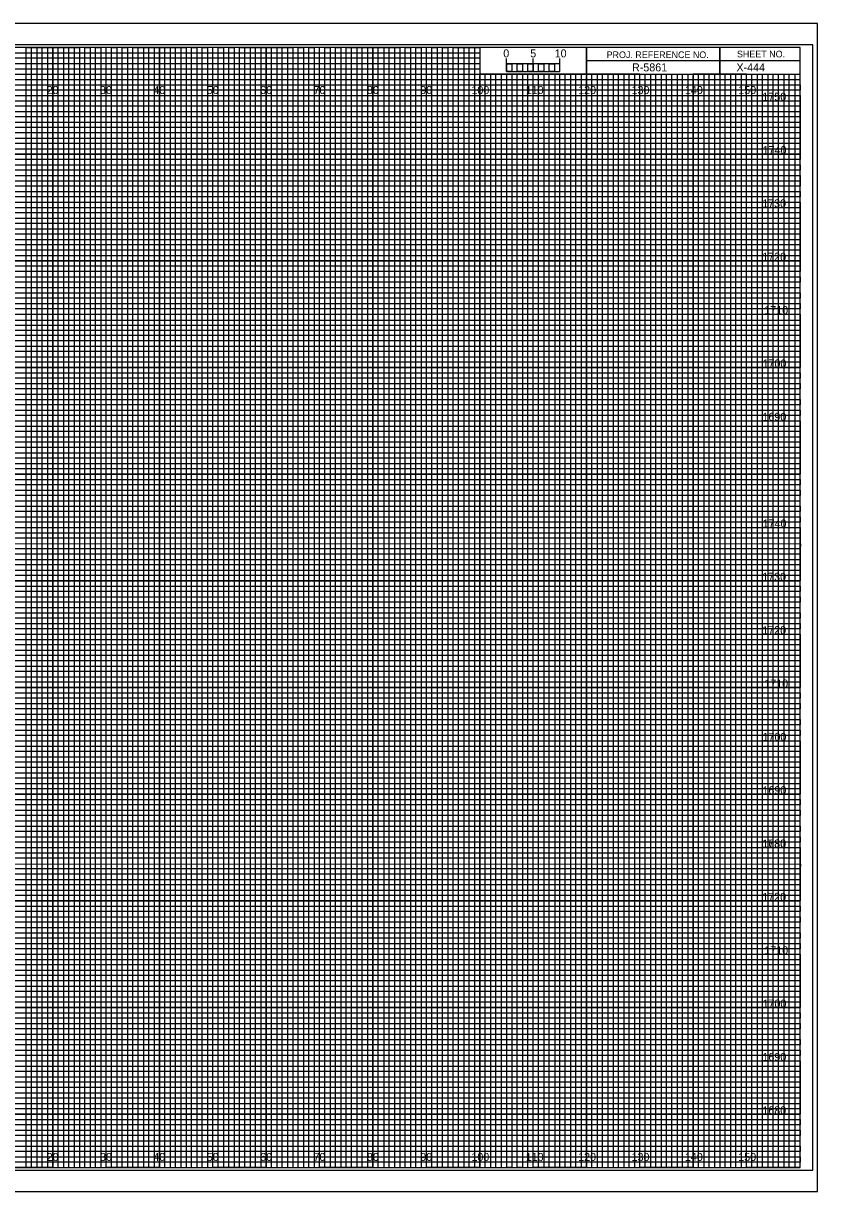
# Model space of a CAD drawing. Extents: x -13 to 323, y -5 to 1314.
# Drawn here: x 174.5 to 323.3, y 655.5 to 874.5 of the extents above; entities that cross this region are included whole.
import ezdxf

# ---------------------------------------------------------------- set-up
doc = ezdxf.new("R2010")
doc.units = 0
for name, color, linetype in [('Prop XS Bar Scale Labels', 7, 'Continuous'), ('Prop XS Project Number', 7, 'Continuous'), ('Prop XS Sheet Number', 7, 'Continuous'), ('Raster_Level_0', 7, 'Continuous'), ('Scratch_Level_3', 7, 'Continuous'), ('Sheet Cross Section CELL', 7, 'Continuous'), ('Sheet Cross Section Grid Major CELL', 7, 'Continuous'), ('Sheet Cross Section Grid Middle CELL', 7, 'Continuous'), ('Sheet Cross Section Grid Minor 1 CELL', 7, 'Continuous'), ('Sheet Cross Section Grid Minor 2 CELL', 7, 'Continuous'), ('Sheet Cross Section Scale CELL', 7, 'Continuous'), ('Sheet Cutting Line CELL', 7, 'Continuous'), ('Sheet DOT Grid CELL', 7, 'Continuous'), ('Sheet Plot Border Inside CELL', 7, 'Continuous'), ('Sheet Plot Border Outside CELL', 7, 'Continuous')]:
    doc.layers.add(name, color=color, linetype=linetype)

msp = doc.modelspace()

# ---------------------------------------------------------------- linework, layer by layer
at = {"layer": 'Sheet Cross Section CELL'}
for p, q in [((305, 870), (305, 865)), ((305, 865), (305, 870)), ((280, 867.5), (280, 865)), ((320, 867.49), (280, 867.49)), ((280, 865), (320, 865))]:
    msp.add_line(p, q, dxfattribs=at)
for points in [[(320, 870), (0, 870), (0, 660), (320, 660)], [(280, 870), (260, 870), (260, 865.03), (280, 865.03)], [(320, 870), (280, 870), (280, 865), (320, 865)]]:
    msp.add_lwpolyline(points, close=True, dxfattribs=at)
at = {"layer": 'Sheet Cross Section Grid Major CELL'}
for p, q in [((190, 870), (180, 870)), ((180, 870), (180, 660)), ((190, 660), (190, 870)), ((210, 870), (200, 870)), ((200, 870), (200, 660)), ((210, 660), (210, 870)), ((230, 870), (220, 870)), ((220, 870), (220, 660)), ((230, 660), (230, 870)), ((250, 870), (240, 870)), ((240, 870), (240, 660)), ((250, 660), (250, 870)), ((260, 870), (260, 660)), ((270, 660), (270, 865)), ((290, 865), (280, 865)), ((280, 865), (280, 660)), ((290, 660), (290, 865)), ((310, 865), (300, 865)), ((300, 865), (300, 660)), ((310, 660), (310, 865)), ((180, 660), (170, 660)), ((200, 660), (190, 660)), ((220, 660), (210, 660)), ((240, 660), (230, 660)), ((260, 660), (250, 660)), ((280, 660), (270, 660)), ((300, 660), (290, 660)), ((320, 660), (310, 660)), ((320, 660), (320, 660))]:
    msp.add_line(p, q, dxfattribs=at)
for points in [[(0, 860), (320, 860), (320, 850), (0, 850)], [(0, 840), (320, 840), (320, 830), (0, 830)], [(0, 820), (320, 820), (320, 810), (0, 810)], [(0, 800), (320, 800), (320, 790), (0, 790)], [(0, 780), (320, 780), (320, 770), (0, 770)], [(0, 760), (320, 760), (320, 750), (0, 750)], [(0, 740), (320, 740), (320, 730), (0, 730)], [(0, 720), (320, 720), (320, 710), (0, 710)], [(0, 700), (320, 700), (320, 690), (0, 690)], [(0, 680), (320, 680), (320, 670), (0, 670)]]:
    msp.add_lwpolyline(points, dxfattribs=at)
at = {"layer": 'Sheet Cross Section Grid Middle CELL'}
for points in [[(165, 660), (175, 660), (175, 870), (185, 870), (185, 660), (195, 660), (195, 870), (205, 870), (205, 660), (215, 660), (215, 870), (225, 870), (225, 660), (235, 660), (235, 870), (245, 870), (245, 660), (255, 660), (255, 870), (259.93, 870), (260, 870), (260, 865), (264.99, 865), (264.99, 660), (275, 660), (275, 865), (285, 865), (285, 660), (295, 660), (295, 865), (305, 865), (305, 660), (315, 660), (315, 865)], [(0, 865), (275, 865)], [(0, 845), (320, 845), (320, 855), (0, 855)], [(0, 825), (320, 825), (320, 835), (0, 835)], [(0, 805), (320, 805), (320, 815), (0, 815)], [(0, 785), (320, 785), (320, 795), (0, 795)], [(0, 765), (320, 765), (320, 775), (0, 775)], [(0, 745), (320, 745), (320, 755), (0, 755)], [(0, 725), (320, 725), (320, 735), (0, 735)], [(0, 705), (320, 705), (320, 715), (0, 715)], [(0, 685), (320, 685), (320, 695), (0, 695)], [(0, 665), (320, 665), (320, 675), (0, 675)]]:
    msp.add_lwpolyline(points, dxfattribs=at)
at = {"layer": 'Sheet Cross Section Grid Minor 1 CELL'}
for p, q in [((0, 869), (260, 869)), ((260, 867.98), (0, 867.98)), ((260, 869), (260, 867.98)), ((0, 867), (260, 867)), ((260, 865.89), (0, 865.89)), ((260, 867), (260, 865.89)), ((0, 864), (320, 864))]:
    msp.add_line(p, q, dxfattribs=at)
for points in [[(0, 863), (270, 863), (320, 863), (320, 862), (0, 862)], [(0, 861), (320, 861), (320, 859), (0, 859)], [(0, 858), (320, 858), (320, 857), (0, 856.98)], [(0, 856), (320, 856), (320, 854), (0, 854)], [(0, 853), (320, 853), (320, 852), (0, 852)], [(0, 851), (320, 851), (320, 849), (0, 849)], [(0, 848), (320, 848), (320, 847), (0, 847)], [(0, 846), (320, 846), (320, 844), (0, 844)], [(0, 843), (320, 843), (320, 842), (0, 842)], [(0, 841), (320, 841), (320, 839), (0, 839)], [(0, 838), (320, 838), (320, 837), (0, 837)], [(0, 836), (320, 836), (320, 833.95), (320, 833), (320, 832), (0, 832)], [(0, 834), (320, 834), (320, 833), (0, 833)], [(0, 831), (320, 831), (320, 829), (0, 829.03)], [(0, 829.03), (320, 829), (320, 828), (0, 828)], [(0, 827), (320, 827), (320, 826), (0, 826)], [(0, 824), (320, 824), (320, 823), (0, 823)], [(0, 822), (320, 822), (320, 821), (0, 821)], [(-0.07, 818.89), (320, 818.89), (320, 817.88), (-0.07, 817.88)], [(0, 817), (320, 817), (320, 816), (0, 816)], [(0, 814), (320, 814), (320, 813), (0, 813)], [(0, 812), (320, 812), (320, 811), (0, 811)], [(0, 809), (320, 809), (320, 808), (0, 808)], [(0, 807), (320, 807), (320, 806), (0, 806)], [(0, 804), (320, 804), (320, 803), (0, 803)], [(0, 802), (320, 802), (320, 801), (0, 801)], [(0, 799), (320, 799), (319.99, 797.98), (0, 798)], [(0, 797), (320, 797), (320, 796), (0, 796)], [(0, 794), (320, 794), (320, 793), (0, 793)], [(0, 792), (320, 792), (320, 791), (0, 791)], [(0, 789), (320, 789), (320, 788), (0, 788)], [(0, 787), (320, 787), (320, 786), (0, 786)], [(0, 784), (320, 784), (320, 783), (0, 783)], [(0, 782), (320, 782), (320, 781), (0, 781)], [(0, 779), (320, 779), (320, 778), (0, 778)], [(0, 776.99), (320.07, 776.91), (320, 776), (0, 776)], [(0, 774), (320, 774), (320, 773), (0, 773)], [(0, 772), (320, 772), (320, 771), (0, 771)], [(0, 769), (320, 769), (320, 768), (0, 768)], [(0, 767), (320, 767), (320, 766), (0, 766)], [(0, 764), (320, 764), (320, 763), (0, 763)], [(0, 762), (320, 762), (320, 761), (0, 761)], [(0, 759), (320, 759), (320, 758), (0, 758)], [(0, 757), (320, 757), (320, 756), (0, 756)], [(0, 754), (320, 754), (320, 753), (0, 753)], [(0, 752), (320, 752), (320, 751), (0, 751)], [(0, 749), (320, 749), (320, 748), (0, 748)], [(0, 747), (320, 747), (320, 746), (0, 746)], [(0, 744), (320, 744), (320, 743), (0, 743)], [(0, 742), (320, 742), (320, 741), (0, 741)], [(0, 739), (320, 739), (319.99, 737.98), (0, 738)], [(0, 737), (320, 737), (320, 736), (0, 736)], [(0, 734), (320, 734), (320, 733), (0, 733)], [(0, 732), (320, 732), (320, 731), (0, 731)], [(0, 729), (320, 729), (320, 728), (0, 728)], [(0, 727), (320, 727), (320, 726), (0, 726)], [(0, 724), (320, 724), (320, 723), (0, 723)], [(0, 722), (320, 722), (320, 721), (0, 721)], [(0, 719), (320, 719), (320, 718), (0, 718)], [(0, 716.99), (320.07, 716.91), (320, 716), (0, 716)], [(0, 714), (320, 714), (320, 713), (0, 713)], [(0, 712), (320, 712), (320, 711), (0, 711)], [(0, 709), (320, 709), (320, 708), (0, 708)], [(0, 707), (320, 707), (320, 706), (0, 706)], [(0, 704), (320, 704), (320, 703), (0, 703)], [(0, 702), (320, 702), (320, 701), (0, 701)], [(0, 699), (320, 699), (320, 698), (0, 698)], [(0, 697), (320, 697), (320, 696), (0, 696)], [(0, 694), (320, 694), (320, 693), (0, 693)], [(0, 692), (320, 692), (320, 691), (0, 691)], [(0, 689), (320, 689), (320, 688), (0, 688)], [(0, 687), (320, 687), (320, 686), (0, 686)], [(0, 684), (320, 684), (320, 683), (0, 683)], [(0, 682), (320, 682), (320, 681), (0, 681)], [(0, 679), (320, 679), (320, 678), (0, 678)], [(0, 677), (320, 677), (320, 676), (0, 676)], [(0, 674), (320, 674), (320, 673), (0, 673)], [(0, 672), (320, 672), (320, 671), (0, 671)], [(0, 669), (320, 669), (320, 668), (0, 668)], [(0, 667), (320, 667), (320, 666), (0, 666)], [(0, 664), (320, 664), (320, 663), (0, 663)], [(0, 662), (320, 662), (320, 661), (0, 661)]]:
    msp.add_lwpolyline(points, dxfattribs=at)
at = {"layer": 'Sheet Cross Section Grid Minor 2 CELL'}
for p, q in [((267, 865), (266.01, 865)), ((266.01, 865), (266.01, 660)), ((267, 660), (267, 865)), ((269, 865), (268, 865)), ((268, 865), (268, 660)), ((269, 660), (269, 865)), ((266.01, 660), (265, 660)), ((268, 660), (267, 660))]:
    msp.add_line(p, q, dxfattribs=at)
for points in [[(175, 660), (176, 660), (176, 870), (177, 870), (177, 660)], [(177, 660), (178, 660), (178, 870), (179, 870), (179, 660)], [(180, 660), (181, 660), (181, 870), (182, 870), (182, 660)], [(182, 660), (183, 660), (183, 870), (184, 870), (184, 660)], [(185, 660), (186, 660), (186, 870), (187, 870), (187, 660)], [(187, 660), (188, 660), (188, 870), (189, 870), (189, 660)], [(190, 660), (191, 660), (191, 870), (192, 870), (192, 660)], [(192, 660), (193, 660), (193, 870), (194, 870), (194, 660)], [(195, 660), (196, 660), (196, 870), (197, 870), (197, 660)], [(197, 660), (198, 660), (198, 870), (199, 870), (199, 660)], [(200, 660), (201, 660), (201, 870), (202, 870), (202, 660)], [(202, 660), (203, 660), (203, 870), (204, 870), (204, 660)], [(205, 660), (206, 660), (206, 870), (207, 870), (207, 660)], [(207, 660), (208, 660), (208, 870), (209, 870), (209, 660)], [(210, 660), (211, 660), (211, 870), (212, 870), (212, 660)], [(212, 660), (213, 660), (213, 870), (214, 870), (214, 660)], [(215, 660), (216, 660), (216, 870), (217, 870), (217, 660)], [(217, 660), (218, 660), (218, 870), (219, 870), (219, 660)], [(220, 660), (221, 660), (221, 870), (222, 870), (222, 660)], [(222, 660), (223, 660), (223, 870), (224, 870), (224, 660)], [(225, 660), (226, 660), (226, 870), (227, 870), (227, 660)], [(227, 660), (228, 660), (228, 870), (229, 870), (229, 660)], [(230, 660), (231, 660), (231, 870), (232, 870), (232, 660)], [(232, 660), (233, 660), (233, 870), (234, 870), (234, 660)], [(235, 660), (236, 660), (236, 870), (237, 870), (237, 660)], [(237, 660), (238, 660), (238, 870), (239, 870), (239, 660)], [(240, 660), (241, 660), (241, 870), (242, 870), (242, 660)], [(242, 660), (243, 660), (243, 870), (244, 870), (244, 660)], [(245, 660), (246, 660), (246, 870), (247, 870), (247, 660)], [(247, 660), (248, 660), (248, 870), (249, 870), (249, 660)], [(250, 660), (251, 660), (251, 870), (252, 870), (252, 660)], [(252, 660), (253, 660), (253, 870), (254, 870), (254, 660)], [(255, 660), (256, 660), (256, 870), (257, 870), (257, 660)], [(257, 660), (258, 660), (258, 870), (259, 870), (259, 660)], [(260, 660), (261, 660), (261, 865), (262.02, 865), (262.02, 660)], [(262, 660), (263, 660), (263, 865), (263.99, 865), (263.99, 660)], [(270, 660), (270.98, 660), (270.98, 865), (272, 865), (272, 660)], [(272, 660), (273, 660), (273, 865), (274.05, 865), (274.05, 660)], [(275, 660), (276, 660), (276, 865), (277, 865), (277, 660)], [(277, 660), (278, 660), (278, 865), (279, 865), (279, 660)], [(280, 660), (281, 660), (281, 865), (282, 865), (282, 660)], [(282, 660), (283, 660), (283, 865), (284, 865), (284, 660)], [(285, 660), (286, 660), (286, 865), (287, 865), (287, 660)], [(287, 660), (288, 660), (288, 865), (289, 865), (289, 660)], [(290, 660), (291, 660), (291, 865), (292, 865), (292, 660)], [(292, 660), (293, 660), (293, 865), (294, 865), (294, 660)], [(295, 660), (296, 660), (296, 865), (297, 865), (297, 660)], [(297, 660), (298, 660), (298, 865), (299, 865), (299, 660)], [(300, 660), (301, 660), (301, 865), (302, 865), (302, 660)], [(302, 660), (303, 660), (303, 865), (304, 865), (304, 660)], [(305, 660), (306, 660), (306, 865), (307, 865), (307, 660)], [(307, 660), (308, 660), (308, 865), (309, 865), (309, 660)], [(310, 660), (311, 660), (311, 865), (312, 865), (312, 660)], [(312, 660), (313, 660), (313, 865), (314, 865), (314, 660)], [(315, 660), (316, 660), (316, 865), (317, 865), (317, 660)], [(317, 660), (318, 660), (318, 865), (319, 865), (319, 660)]]:
    msp.add_lwpolyline(points, dxfattribs=at)
at = {"layer": 'Sheet Cross Section Scale CELL'}
for p, q in [((265, 865.49), (265, 867.9)), ((265, 866.9), (265, 867.9)), ((270, 865.49), (270, 867.9)), ((275, 865.49), (275, 867.9)), ((275, 866.9), (275, 867.9))]:
    msp.add_line(p, q, dxfattribs=at)
for points in [[(275, 866.9), (265, 866.9), (265, 865.49), (275, 865.49)], [(265, 866.9), (266, 866.9), (266, 865.49), (265, 865.49)], [(267, 866.9), (268, 866.9), (268, 865.49), (267, 865.49)], [(269, 866.9), (270, 866.9), (270, 865.49), (269, 865.49)], [(271, 866.9), (272, 866.9), (272, 865.49), (271, 865.49)], [(273, 866.9), (274, 866.9), (274, 865.49), (273, 865.49)]]:
    msp.add_lwpolyline(points, close=True, dxfattribs=at)
at = {"layer": 'Sheet Cutting Line CELL'}
for p, q in [((323.3, 874.5), (-13.4, 874.5)), ((-13.4, 655.5), (323.3, 655.5))]:
    msp.add_line(p, q, dxfattribs=at)
at = {"layer": 'Sheet DOT Grid CELL'}
for p, q in [((180, 660), (180, 870)), ((190, 660), (190, 870)), ((200, 660), (200, 870)), ((210, 660), (210, 870)), ((220, 660), (220, 870)), ((230, 660), (230, 870)), ((240, 660), (240, 870)), ((250, 660), (250, 870)), ((260, 660), (260, 864.69)), ((270, 660), (270, 864.69)), ((280, 660), (280, 864.69)), ((290, 660), (290, 864.69)), ((300, 660), (300, 864.69)), ((310, 660), (310, 864.69)), ((0, 860), (320, 860)), ((0, 850), (320, 850)), ((0, 840), (320, 840)), ((0, 830), (320, 830)), ((0, 820), (320, 820)), ((0, 810), (320, 810)), ((0, 800), (320, 800)), ((0, 790), (320, 790)), ((0, 780), (320, 780)), ((0, 770), (320, 770)), ((0, 760), (320, 760)), ((0, 750), (320, 750)), ((0, 740), (320, 740)), ((0, 730), (320, 730)), ((0, 720), (320, 720)), ((0, 710), (320, 710)), ((0, 700), (320, 700)), ((0, 690), (320, 690)), ((0, 680), (320, 680)), ((0, 670), (320, 670))]:
    msp.add_line(p, q, dxfattribs=at)
at = {"layer": 'Sheet Plot Border Inside CELL'}
msp.add_lwpolyline([(-10.8, 659.5), (322.4, 659.5), (322.4, 870.5), (-10.8, 870.5)], close=True, dxfattribs=at)
at = {"layer": 'Sheet Plot Border Outside CELL'}
msp.add_lwpolyline([(-13.4, 655.5), (323.3, 655.5), (323.3, 874.5), (-13.4, 874.5)], close=True, dxfattribs=at)

# ---------------------------------------------------------------- texts
at = {"layer": 'Prop XS Bar Scale Labels'}
for s, p in [('5', (269.47, 868.12)), ('10', (274.04, 868.12))]:
    msp.add_text(s, height=1.5, dxfattribs=at).set_placement(p)
at = {"layer": 'Prop XS Project Number'}
msp.add_text('R-5861', height=1.5, dxfattribs=at).set_placement((288.53, 865.5))
at = {"layer": 'Prop XS Sheet Number'}
msp.add_text('X-444', height=1.5, dxfattribs=at).set_placement((308.09, 865.5))
at = {"layer": 'Raster_Level_0'}
for s, p in [('20', (178.86, 861.25)), ('30', (188.86, 861.25)), ('40', (198.86, 861.25)), ('50', (208.86, 861.25)), ('60', (218.86, 861.25)), ('70', (228.86, 861.25)), ('80', (238.86, 861.25)), ('90', (248.86, 861.25)), ('100', (258.44, 861.25)), ('110', (268.62, 861.25)), ('120', (278.44, 861.25)), ('130', (288.44, 861.25)), ('140', (298.44, 861.25)), ('150', (308.44, 861.25)), ('20', (178.86, 661.25)), ('30', (188.86, 661.25)), ('40', (198.86, 661.25)), ('50', (208.86, 661.25)), ('60', (218.86, 661.25)), ('70', (228.86, 661.25)), ('80', (238.86, 661.25)), ('90', (248.86, 661.25)), ('100', (258.44, 661.25)), ('110', (268.62, 661.25)), ('120', (278.44, 661.25)), ('130', (288.44, 661.25)), ('140', (298.44, 661.25)), ('150', (308.44, 661.25))]:
    msp.add_text(s, height=1.5, dxfattribs=at).set_placement(p)
at = {"layer": 'Scratch_Level_3'}
for s, p in [('1750', (312.96, 860)), ('1740', (313, 850)), ('1730', (312.92, 840)), ('1720', (312.93, 830)), ('1710', (313.31, 820)), ('1700', (312.98, 810)), ('1690', (312.97, 800)), ('1740', (313, 780)), ('1730', (312.92, 770)), ('1720', (312.93, 760)), ('1710', (313.31, 750)), ('1700', (312.98, 740)), ('1690', (312.97, 730)), ('1730', (312.92, 720)), ('1680', (312.95, 720)), ('1720', (312.93, 710)), ('1710', (313.31, 700)), ('1700', (312.98, 690)), ('1690', (312.97, 680)), ('1680', (312.95, 670))]:
    msp.add_text(s, height=1.5, dxfattribs=at).set_placement(p)
at = {"layer": 'Sheet Cross Section CELL'}
for s, p in [('PROJ. REFERENCE NO.', (283.77, 867.99)), ('SHEET NO.', (308.19, 868.12))]:
    msp.add_text(s, height=1.25, dxfattribs=at).set_placement(p)
at = {"layer": 'Sheet Cross Section Scale CELL'}
msp.add_text('0', height=1.5, dxfattribs=at).set_placement((264.41, 868.12))

doc.saveas('drawing.dxf')
